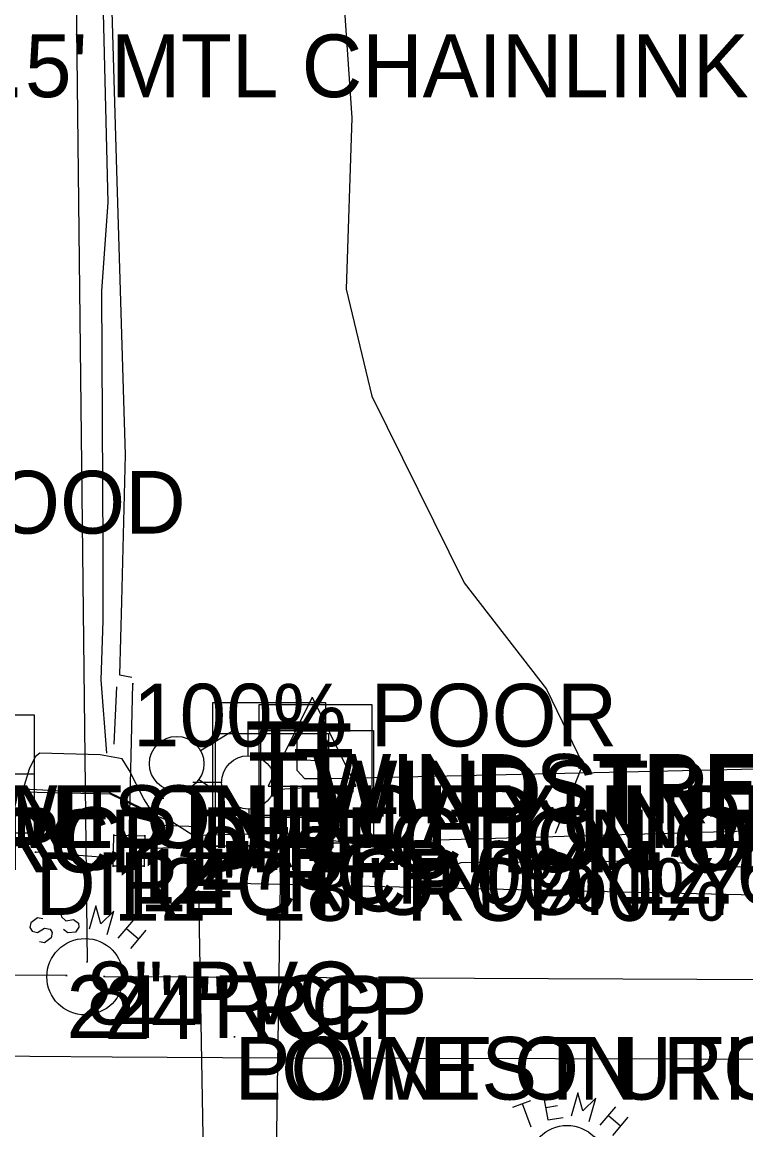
# Model space of a CAD drawing. Extents: x 1304270 to 1306561, y 1876019 to 1876752.
# Drawn here: x 1304977.1 to 1305034.9, y 1876403.7 to 1876492.1 of the extents above; entities that cross this region are included whole.
import ezdxf

# ---------------------------------------------------------------- set-up
doc = ezdxf.new("R2010")
doc.units = 0
for name, color, linetype in [('S_BUILDING_ANNOT', 7, 'Continuous'), ('S_DITCHLINE', 7, 'Continuous'), ('S_DRG_PT_SYM', 7, 'Continuous'), ('S_DRIVEWAY', 7, 'Continuous'), ('S_DROP_INLET', 7, 'Continuous'), ('S_EDGE_CONCRETE', 7, 'Continuous'), ('S_EDGE_PAVEMENT', 7, 'Continuous'), ('S_ELECTRIC_UTILITIES_ANNOT', 7, 'Continuous'), ('S_FIBER_OPTIC_CABLE', 7, 'Continuous'), ('S_GATE_ANNOT', 7, 'Continuous'), ('S_MSC_PT_SYM', 7, 'Continuous'), ('S_PAVEMENT_CROWN', 7, 'Continuous'), ('S_SANITARY_SEWER', 7, 'Continuous'), ('S_SANITARY_SEWER_ANNOT', 7, 'Continuous'), ('S_SIDE_DRAIN', 7, 'Continuous'), ('S_SIDE_DRAIN_ANNOT', 7, 'Continuous'), ('S_STORM_SEWER_ANNOT', 7, 'Continuous'), ('S_SURVEY_TEXT_ANNOT', 7, 'Continuous'), ('S_TELEPHONE_UTILITIES', 7, 'Continuous'), ('S_TELEPHONE_UTILITIES_ANNOT', 7, 'Continuous'), ('S_UTILITY_POLE', 7, 'Continuous'), ('S_UTILITY_POLE_ANNOT', 7, 'Continuous'), ('S_UTL_PT_SYM', 7, 'Continuous'), ('S_WATER_UTILITIES', 7, 'Continuous'), ('S_WATER_UTILITIES_ANNOT', 7, 'Continuous')]:
    doc.layers.add(name, color=color, linetype=linetype)

msp = doc.modelspace()

# ---------------------------------------------------------------- linework, layer by layer
at = {"layer": 'S_DITCHLINE'}
for points in [[(1304983.879, 1876561.903), (1304983.511, 1876548.33), (1304984.113, 1876535.99), (1304984.548, 1876517.678), (1304983.917, 1876504.779), (1304984.619, 1876481.176), (1304985.32, 1876457.574), (1304985.049, 1876445.871), (1304984.883, 1876440.018), (1304985.87, 1876439.839)], [(1304984.468, 1876434.497), (1304984.676, 1876439.078)]]:
    msp.add_lwpolyline(points, dxfattribs=at)
at = {"layer": 'S_DRG_PT_SYM'}
for points in [[(1304985.954, 1876439.313), (1304985.954, 1876439.363), (1304985.954, 1876439.313), (1304985.904, 1876439.313), (1304985.954, 1876439.313), (1304985.954, 1876439.263), (1304985.954, 1876439.313), (1304986.005, 1876439.313)], [(1304984.417, 1876427.242), (1304984.417, 1876427.292), (1304984.417, 1876427.242), (1304984.367, 1876427.242), (1304984.417, 1876427.242), (1304984.417, 1876427.192), (1304984.417, 1876427.242), (1304984.467, 1876427.242)], [(1304986.891, 1876427.183), (1304986.891, 1876427.233), (1304986.891, 1876427.183), (1304986.841, 1876427.183), (1304986.891, 1876427.183), (1304986.891, 1876427.133), (1304986.891, 1876427.183), (1304986.941, 1876427.183)], [(1304985.647, 1876426.765), (1304985.647, 1876426.815), (1304985.647, 1876426.765), (1304985.596, 1876426.765), (1304985.647, 1876426.765), (1304985.647, 1876426.715), (1304985.647, 1876426.765), (1304985.697, 1876426.765)], [(1304986.495, 1876426.155), (1304986.495, 1876426.205), (1304986.495, 1876426.155), (1304986.445, 1876426.155), (1304986.495, 1876426.155), (1304986.495, 1876426.105), (1304986.495, 1876426.155), (1304986.545, 1876426.155)], [(1304978.165, 1876425.878), (1304978.165, 1876425.928), (1304978.165, 1876425.878), (1304978.115, 1876425.878), (1304978.165, 1876425.878), (1304978.165, 1876425.828), (1304978.165, 1876425.878), (1304978.215, 1876425.878)], [(1304984.41, 1876425.404), (1304984.41, 1876425.454), (1304984.41, 1876425.404), (1304984.36, 1876425.404), (1304984.41, 1876425.404), (1304984.41, 1876425.354), (1304984.41, 1876425.404), (1304984.46, 1876425.404)], [(1304984.371, 1876424.751), (1304984.371, 1876424.801), (1304984.371, 1876424.751), (1304984.321, 1876424.751), (1304984.371, 1876424.751), (1304984.371, 1876424.701), (1304984.371, 1876424.751), (1304984.421, 1876424.751)], [(1304986.838, 1876424.759), (1304986.838, 1876424.809), (1304986.838, 1876424.759), (1304986.788, 1876424.759), (1304986.838, 1876424.759), (1304986.838, 1876424.709), (1304986.838, 1876424.759), (1304986.888, 1876424.759)]]:
    msp.add_lwpolyline(points, dxfattribs=at)
at = {"layer": 'S_DRIVEWAY'}
msp.add_lwpolyline([(1305002.462, 1876498.47), (1305003.418, 1876484.461), (1305002.967, 1876470.781), (1305005.014, 1876462.252), (1305012.384, 1876447.357), (1305018.949, 1876438.877), (1305021.85, 1876432.888), (1305019.653, 1876427.358)], dxfattribs=at)
at = {"layer": 'S_DROP_INLET'}
for p, q in [((1304984.371, 1876424.751), (1304984.417, 1876427.242)), ((1304984.417, 1876427.242), (1304986.891, 1876427.183)), ((1304986.891, 1876427.183), (1304986.838, 1876424.759)), ((1304986.838, 1876424.759), (1304984.371, 1876424.751))]:
    msp.add_line(p, q, dxfattribs=at)
at = {"layer": 'S_EDGE_CONCRETE'}
for points in [[(1304987.571, 1876428.974), (1304986.831, 1876430.129), (1304985.64, 1876432.413), (1304985.086, 1876433.316), (1304983.347, 1876433.645), (1304978.524, 1876433.786), (1304978.159, 1876433.477), (1304977.674, 1876432.511), (1304977.197, 1876430.928), (1304981.925, 1876430.682), (1304983.986, 1876430.687), (1304987.487, 1876428.985)], [(1304987.487, 1876428.985), (1304987.571, 1876428.974)]]:
    msp.add_lwpolyline(points, dxfattribs=at)
at = {"layer": 'S_EDGE_PAVEMENT'}
for points in [[(1304983.88, 1876433.765), (1304983.407, 1876439.631), (1304983.579, 1876444.332), (1304983.568, 1876450), (1304983.474, 1876470.668), (1304983.963, 1876477.711), (1304983.554, 1876495.007), (1304983.144, 1876512.302), (1304982.902, 1876528.292), (1304982.66, 1876544.281), (1304982.058, 1876559.301)], [(1304919.779, 1876431.718), (1304944.538, 1876430.873), (1304948.222, 1876430.692), (1304950.692, 1876430.942), (1304957.212, 1876430.901), (1304966.928, 1876430.679), (1304977.139, 1876430.697), (1304984.136, 1876430.53), (1304987.418, 1876428.94), (1304989.146, 1876428.281), (1304990.755, 1876427.243), (1304997.978, 1876427.391), (1305006.508, 1876426.141), (1305007.367, 1876424.801), (1305008.544, 1876424.166), (1305009.948, 1876424.231), (1305012.143, 1876425.041), (1305027.35, 1876425.193), (1305037.635, 1876424.503)]]:
    msp.add_lwpolyline(points, dxfattribs=at)
at = {"layer": 'S_FIBER_OPTIC_CABLE'}
for p, q in [((1305054.078, 1876432.909), (1305001.626, 1876431.73)), ((1304997.811, 1876430.577), (1304997.1, 1876382.101))]:
    msp.add_line(p, q, dxfattribs=at)
at = {"layer": 'S_MSC_PT_SYM'}
msp.add_lwpolyline([(1304994.061, 1876411.136), (1304994.061, 1876411.186), (1304994.061, 1876411.136), (1304994.011, 1876411.136), (1304994.061, 1876411.136), (1304994.061, 1876411.086), (1304994.061, 1876411.136), (1304994.111, 1876411.136)], dxfattribs=at)
at = {"layer": 'S_PAVEMENT_CROWN'}
msp.add_lwpolyline([(1304919.661, 1876411.009), (1304932.568, 1876410.532), (1304945.474, 1876410.055), (1304958.299, 1876409.86), (1304971.123, 1876409.666), (1304984.305, 1876409.563), (1304997.488, 1876409.46), (1305019.679, 1876409.408), (1305041.87, 1876409.356), (1305062.985, 1876409.225), (1305084.101, 1876409.095), (1305104.326, 1876408.423), (1305118.333, 1876408.238), (1305132.34, 1876408.054), (1305154.417, 1876408.065)], dxfattribs=at)
at = {"layer": 'S_SANITARY_SEWER'}
for p, q in [((1304980.604, 1876568.002), (1304982.287, 1876417.142)), ((1304977.804, 1876420.246), (1304977.727, 1876419.858)), ((1304978.347, 1876420.633), (1304977.804, 1876420.246)), ((1304978.773, 1876420.556), (1304978.347, 1876420.633)), ((1304984.779, 1876419.006), (1304986.019, 1876420.478)), ((1304977.727, 1876419.858), (1304977.921, 1876419.587)), ((1304977.921, 1876419.587), (1304978.347, 1876419.471)), ((1304978.347, 1876419.471), (1304978.889, 1876419.819)), ((1304978.889, 1876419.819), (1304979.354, 1876419.742)), ((1304979.432, 1876419.044), (1304978.889, 1876418.657)), ((1304979.354, 1876419.742), (1304979.509, 1876419.471)), ((1304979.509, 1876419.471), (1304979.432, 1876419.044)), ((1304985.438, 1876419.781), (1304986.407, 1876418.967)), ((1304986.988, 1876419.664), (1304985.748, 1876418.192)), ((1304978.889, 1876418.657), (1304978.502, 1876418.734)), ((1304980.649, 1876416.046), (1304699.882, 1876417.28)), ((1304983.663, 1876415.964), (1305346.234, 1876414.239))]:
    msp.add_line(p, q, dxfattribs=at)
for points in [[(1304981.447, 1876421.176), (1304981.098, 1876421.447), (1304980.439, 1876421.369), (1304980.207, 1876421.021), (1304980.246, 1876420.711), (1304980.594, 1876420.401), (1304981.214, 1876420.517), (1304981.602, 1876420.207), (1304981.641, 1876419.897), (1304981.369, 1876419.509), (1304980.749, 1876419.432), (1304980.401, 1876419.703)], [(1304983.888, 1876419.316), (1304984.431, 1876421.176), (1304983.384, 1876420.168), (1304982.997, 1876421.602), (1304982.454, 1876419.742)]]:
    msp.add_lwpolyline(points, dxfattribs=at)
msp.add_circle((1304982.131, 1876415.942), 3.048, dxfattribs=at)
at = {"layer": 'S_SIDE_DRAIN'}
for p, q in [((1304985.647, 1876426.765), (1304985.954, 1876439.313)), ((1305054.281, 1876428.116), (1304986.495, 1876426.155)), ((1304984.41, 1876425.404), (1304978.165, 1876425.878))]:
    msp.add_line(p, q, dxfattribs=at)
at = {"layer": 'S_TELEPHONE_UTILITIES'}
for p, q in [((1304997.055, 1876433.331), (1304997.279, 1876430.872)), ((1305000.755, 1876433.169), (1304997.055, 1876433.331)), ((1305000.875, 1876431.115), (1305000.755, 1876433.169)), ((1304997.279, 1876430.872), (1305000.875, 1876431.115))]:
    msp.add_line(p, q, dxfattribs=at)
for points in [[(1304992.327, 1876428.813), (1304992.327, 1876437.813), (1305001.327, 1876437.813), (1305001.327, 1876428.813)], [(1304996.027, 1876428.651), (1304996.027, 1876437.651), (1305005.027, 1876437.651), (1305005.027, 1876428.651)], [(1304992.551, 1876426.354), (1304992.551, 1876435.354), (1305001.551, 1876435.354), (1305001.551, 1876426.354)], [(1304996.147, 1876426.597), (1304996.147, 1876435.597), (1305005.147, 1876435.597), (1305005.147, 1876426.597)]]:
    msp.add_lwpolyline(points, close=True, dxfattribs=at)
at = {"layer": 'S_TELEPHONE_UTILITIES_ANNOT'}
for p, q in [((1305019.95, 1876406.649), (1305018.71, 1876406.416)), ((1305016.269, 1876405.525), (1305017.702, 1876406.068)), ((1305017.005, 1876405.835), (1305017.702, 1876403.975)), ((1305018.71, 1876406.416), (1305019.059, 1876404.518)), ((1305019.834, 1876405.641), (1305018.904, 1876405.486)), ((1305023.244, 1876404.091), (1305024.484, 1876405.564)), ((1305019.059, 1876404.518), (1305020.299, 1876404.711)), ((1305023.902, 1876404.866), (1305024.871, 1876404.053)), ((1305025.452, 1876404.75), (1305024.212, 1876403.278))]:
    msp.add_line(p, q, dxfattribs=at)
msp.add_lwpolyline([(1305022.352, 1876404.401), (1305022.895, 1876406.261), (1305021.849, 1876405.254), (1305021.461, 1876406.688), (1305020.919, 1876404.828)], dxfattribs=at)
msp.add_circle((1305020.595, 1876401.028), 3.048, dxfattribs=at)
at = {"layer": 'S_UTILITY_POLE'}
for p, q in [((1305000.265, 1876438.238), (1304996.738, 1876431.146)), ((1305000.265, 1876438.238), (1305003.752, 1876431.146)), ((1304995.157, 1876433.556), (1304995.157, 1876435.804)), ((1304999.063, 1876432.386), (1304999.063, 1876434.828)), ((1305001.427, 1876434.828), (1305001.427, 1876432.386)), ((1304999.683, 1876431.728), (1304999.063, 1876432.386)), ((1305001.427, 1876432.386), (1305000.885, 1876431.728)), ((1304993.064, 1876431.425), (1304990.739, 1876431.425)), ((1305000.885, 1876431.728), (1304999.683, 1876431.728)), ((1304996.738, 1876431.146), (1305003.752, 1876431.146)), ((1304995.234, 1876427.007), (1304995.234, 1876429.332))]:
    msp.add_line(p, q, dxfattribs=at)
msp.add_circle((1304995.159, 1876431.446), 2.128, dxfattribs=at)
at = {"layer": 'S_UTL_PT_SYM'}
for points in [[(1305001.626, 1876431.73), (1305001.626, 1876431.78), (1305001.626, 1876431.73), (1305001.576, 1876431.73), (1305001.626, 1876431.73), (1305001.626, 1876431.68), (1305001.626, 1876431.73), (1305001.676, 1876431.73)], [(1304997.811, 1876430.577), (1304997.811, 1876430.627), (1304997.811, 1876430.577), (1304997.76, 1876430.577), (1304997.811, 1876430.577), (1304997.811, 1876430.527), (1304997.811, 1876430.577), (1304997.86, 1876430.577)], [(1304987.962, 1876427.995), (1304987.962, 1876428.045), (1304987.962, 1876427.995), (1304987.912, 1876427.995), (1304987.962, 1876427.995), (1304987.962, 1876427.944), (1304987.962, 1876427.995), (1304988.012, 1876427.995)], [(1304991.239, 1876427.897), (1304991.239, 1876427.947), (1304991.239, 1876427.897), (1304991.189, 1876427.897), (1304991.239, 1876427.897), (1304991.239, 1876427.846), (1304991.239, 1876427.897), (1304991.289, 1876427.897)], [(1304985.772, 1876425.704), (1304985.772, 1876425.754), (1304985.772, 1876425.704), (1304985.721, 1876425.704), (1304985.772, 1876425.704), (1304985.772, 1876425.654), (1304985.772, 1876425.704), (1304985.822, 1876425.704)], [(1304991.145, 1876423.389), (1304991.145, 1876423.439), (1304991.145, 1876423.389), (1304991.095, 1876423.389), (1304991.145, 1876423.389), (1304991.145, 1876423.339), (1304991.145, 1876423.389), (1304991.195, 1876423.389)], [(1304991.8, 1876423.431), (1304991.8, 1876423.481), (1304991.8, 1876423.431), (1304991.75, 1876423.431), (1304991.8, 1876423.431), (1304991.8, 1876423.381), (1304991.8, 1876423.431), (1304991.85, 1876423.431)], [(1304991.182, 1876422.775), (1304991.182, 1876422.825), (1304991.182, 1876422.775), (1304991.132, 1876422.775), (1304991.182, 1876422.775), (1304991.182, 1876422.725), (1304991.182, 1876422.775), (1304991.232, 1876422.775)], [(1304982.287, 1876417.142), (1304982.287, 1876417.192), (1304982.287, 1876417.142), (1304982.237, 1876417.142), (1304982.287, 1876417.142), (1304982.287, 1876417.092), (1304982.287, 1876417.142), (1304982.337, 1876417.142)], [(1304980.649, 1876416.046), (1304980.649, 1876416.096), (1304980.649, 1876416.046), (1304980.599, 1876416.046), (1304980.649, 1876416.046), (1304980.649, 1876415.996), (1304980.649, 1876416.046), (1304980.699, 1876416.046)], [(1304982.345, 1876415.9), (1304982.345, 1876415.951), (1304982.345, 1876415.9), (1304982.295, 1876415.9), (1304982.345, 1876415.9), (1304982.345, 1876415.85), (1304982.345, 1876415.9), (1304982.395, 1876415.9)], [(1304983.663, 1876415.964), (1304983.663, 1876416.014), (1304983.663, 1876415.964), (1304983.613, 1876415.964), (1304983.663, 1876415.964), (1304983.663, 1876415.914), (1304983.663, 1876415.964), (1304983.713, 1876415.964)], [(1304994.061, 1876411.136), (1304994.061, 1876411.186), (1304994.061, 1876411.136), (1304994.011, 1876411.136), (1304994.061, 1876411.136), (1304994.061, 1876411.086), (1304994.061, 1876411.136), (1304994.111, 1876411.136)]]:
    msp.add_lwpolyline(points, dxfattribs=at)
at = {"layer": 'S_WATER_UTILITIES'}
for p, q in [((1304968.664, 1876436.824), (1304978.081, 1876436.824)), ((1304978.081, 1876436.824), (1304978.081, 1876427.407)), ((1304991.344, 1876433.99), (1304994.167, 1876435.722)), ((1304968.664, 1876432.135), (1304978.081, 1876432.135)), ((1304991.22, 1876431.681), (1304994.129, 1876429.754)), ((1304991.239, 1876427.897), (1304987.962, 1876427.995)), ((1304991.145, 1876423.389), (1304991.239, 1876427.897)), ((1304978.081, 1876427.407), (1304968.664, 1876427.407)), ((1305048.968, 1876422.166), (1304991.8, 1876423.431)), ((1304991.182, 1876422.775), (1304992.308, 1876358.601))]:
    msp.add_line(p, q, dxfattribs=at)
msp.add_circle((1304989.44, 1876432.935), 2.177, dxfattribs=at)

# ---------------------------------------------------------------- texts
at = {"layer": 'S_BUILDING_ANNOT'}
msp.add_text('1 STR BRICK/WOOD', height=5, dxfattribs=at).set_placement((1304925.525, 1876451.298))
at = {"layer": 'S_ELECTRIC_UTILITIES_ANNOT'}
for p in [(1304964.706, 1876426.208), (1304994.061, 1876406.136)]:
    msp.add_text('POINT ON ROAD UNDER LOWES', height=5, dxfattribs=at).set_placement(p)
at = {"layer": 'S_GATE_ANNOT'}
msp.add_text("4' 2.5' MTL CHAINLINK GT", height=5, dxfattribs=at).set_placement((1304964.907, 1876486.11))
at = {"layer": 'S_SANITARY_SEWER_ANNOT'}
for s, p in [('8" PVC', (1304982.287, 1876412.142)), ('24" RCP', (1304980.649, 1876411.046)), ('24" RCP', (1304983.663, 1876410.964))]:
    msp.add_text(s, height=5, dxfattribs=at).set_placement(p)
at = {"layer": 'S_SIDE_DRAIN_ANNOT'}
for s, p in [('100% POOR', (1304985.954, 1876434.313)), ('12" RCP 0% 12.66', (1304985.647, 1876421.765)), ('14" RCP 0%', (1304986.495, 1876421.155)), ('DIRECTION ONLY', (1304978.165, 1876420.878)), ('12" 18" RCP 0% DI 18"', (1304984.41, 1876420.404))]:
    msp.add_text(s, height=5, dxfattribs=at).set_placement(p)
at = {"layer": 'S_STORM_SEWER_ANNOT'}
for p in [(1304962.756, 1876424.271), (1304963.774, 1876424.465)]:
    msp.add_text('18" RCP DIRECTION ONLY', height=5, dxfattribs=at).set_placement(p)
at = {"layer": 'S_SURVEY_TEXT_ANNOT'}
for p in [(1304964.707, 1876426.208), (1304994.061, 1876406.136)]:
    msp.add_text('LOWEST UTILITY LINE', height=5, dxfattribs=at).set_placement(p)
at = {"layer": 'S_TELEPHONE_UTILITIES'}
for p in [(1304994.89, 1876430.313), (1304998.59, 1876430.151), (1304998.71, 1876428.097), (1304995.114, 1876427.854)]:
    msp.add_text('T', height=6, rotation=360, dxfattribs=at).set_placement(p)
at = {"layer": 'S_TELEPHONE_UTILITIES_ANNOT'}
msp.add_text('WINDSTREAM FOC JUNCTION', height=5, dxfattribs=at).set_placement((1305000.755, 1876428.169))
at = {"layer": 'S_UTILITY_POLE_ANNOT'}
msp.add_text('WINDSTREAM FOC MARKER', height=5, dxfattribs=at).set_placement((1305000.265, 1876428.704))
at = {"layer": 'S_WATER_UTILITIES_ANNOT'}
msp.add_text('273', height=5, dxfattribs=at).set_placement((1304991.239, 1876422.897))

doc.saveas('drawing.dxf')
